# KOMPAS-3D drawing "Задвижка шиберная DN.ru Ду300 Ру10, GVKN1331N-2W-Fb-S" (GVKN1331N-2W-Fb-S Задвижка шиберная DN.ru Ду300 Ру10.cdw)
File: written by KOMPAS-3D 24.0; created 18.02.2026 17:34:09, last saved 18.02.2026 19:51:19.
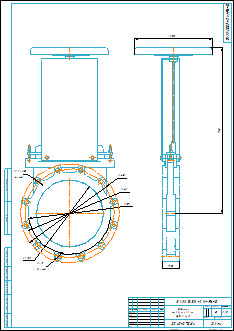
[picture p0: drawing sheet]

Document properties: art: D040-07884; Автор: R2D2; Форматы листов документа: A2; Полное имя файла: GVKN1331N-2W-Fb-S Задвижка шиберная DN.ru Ду300 Ру10.m3d; Масса: 49; Наименование: Задвижка шиберная DN.ru Ду300 Ру10; Количество листов документа: 1; Примечание: D040-07884

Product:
- Part/product: Задвижка шиберная DN.ru Ду300 Ру10  | designation GVKN1331N-2W-Fb-S
    Масса: 49
    Раздел спецификации: Прочие изделия
    Примечание: D040-07884
    additional columns: D040-07884

Views: Вид 1, Спереди, Проекционный вид 2
Referenced files in E:\Работа\Зайцев\GVKN1331N-2W-Fb-S Задвижка шиберная DN.ru Ду50-300 Ру10\DN300\: GVKN1331N-2W-Fb-S Задвижка шиберная DN.ru Ду300 Ру10.m3d
Referenced files in E:\Работа\Зайцев\Для компаса\: чертеж DN.ru.cdt
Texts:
  GVKN1331N-2W-Fb-S
  чертеж DN.ru.cdt
  Задвижка
  шиберная DN.ru
  Ду300 Ру10
  prop
  Задвижка шиберная DN.ru Ду300 Ру10
  GVKN1331N-2W-Fb-S Задвижка шиберная DN.ru Ду300 Ру10
Dimensions and other numbers on the sheet: 0; 3; 2; 4; 370; 23; 8 отв.; 300; 20; 4 отв.; 76; 745; 350; 445; 400; 1:2,5; 1; 49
